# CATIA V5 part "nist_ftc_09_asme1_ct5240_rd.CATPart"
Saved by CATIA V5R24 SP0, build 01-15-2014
Part number: NIST PMI FTC 09 ASME1
Revision: D
Description: NIST PMI test model downloaded from http://go.usa.gov/mGVm
Bounding box of the stored display mesh (mm): x -95.25 to 95.25, y 0 to 3.038, z -139.7 to 139.7
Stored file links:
  C:\work\NIST\DCC_review\nist_ftc_09_asme1_ct5240_rd.CATPart
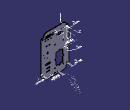
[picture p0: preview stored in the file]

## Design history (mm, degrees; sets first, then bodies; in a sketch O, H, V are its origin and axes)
f4a2d38f3ddc11d3a929006094b99c4b_11 "CATTPSSet"
TTRSSet1
Set1 "MBD_A_PMI"
  Plane1: type Equation, A -0.57735, B 0.57735, C 0.57735, Length 20, RefPoint vertex [face of Chamfer4 | end face of Pad1 | face of Pad1 from Sketch7.L15]
  Point1: type Center, Curve edge [end face of Pad1 | face of Chamfer1]
  Plane2: type OffsetPt, RefPlane face of Pad1 from Sketch7.L15, RefPoint Point1
  Intersect1: ToIntersect1 Chamfer1, ToIntersect2 Plane2
Set2 "MBD_B"
  Sketch1 on end face of Pad1, origin (0, 3.0378, 0), H (-1, 0, 0), V (0, 0, 1)
    arc A1 centre (-50.8, 12.7) radius 34.29 from (-66.509, -17.78) to (-81.28, -3.009) ccw
    point P1 (-50.8, 12.7)
    point P2 (-81.28, -3.009)
    point P3 (-66.509, -17.78)
    line L1 (-64.0699, -20.2137) -> (-63.1677, -17.9758)
    point P5 (-63.1677, -17.9758)
    line L2 (-81.28, -3.009) -> (-83.717, -0.5681)
    line L3 (-83.717, -0.5681) -> (-81.4789, 0.334)
    line L4 (-81.4789, 0.334) -> (-81.28, -3.009)
    polyline C1
    construction line L5 (-50.8, 12.7) -> (-53.3201, 12.7)
    construction line L6 (-50.8, 12.7) -> (-50.8, 10.3697)
    reference projected arc E1 centre (-50.8, 12.7) radius 4.7625 from (-52.578, 17.1182) to (-49.022, 17.1182) ccw from edge [end face of Pad1 | face of Pocket2 from Sketch15.A1]
    point P10 (-63.6219, -19.1025)
    line L7 (-66.509, -17.78) -> (-63.1677, -17.9758)
    line L8 (-66.5086, -17.7802) -> (-64.0704, -20.2149)
    point P12 (-66.5086, -17.7802)
    point P13 (-64.0704, -20.2149)
    radius A1 = 34.29
    distance L5 P3 = 30.48
    distance L6 P2 = 30.48
    length L1 = 2.413
    distance L1 P3 = 3.1722
    angle L1 L7 = 71.3955
    length L8 = 3.4456
    angle L8 L1 = 67
    length L3 = 2.413
    distance L3 P2 = 3.175
    angle L3 L2 = 67
    coincidence: L1 P1, L3 P1, P10 L1, P10 A1, L7 P5, P12 A1, P13 L1
    horizontal: L5 H
    vertical: L6 V
    concentricity: E1 P1
  Sketch2 on end face of Pad1, origin (0, 3.0378, 0), H (-1, 0, 0), V (0, 0, 1)
    reference projected circle E1 centre (57.15, 38.4) radius 3.175 from edge [end face of Pad1 | face of RectPattern2]
    reference projected circle E2 centre (0.15, -101.6) radius 3.175 from edge [end face of Pad1 | face of RectPattern2]
    axis line L1 (0.15, -101.6) -> (57.15, 38.4)
    point P1 (0.15, -101.6)
    point P2 (57.15, 38.4)
    point P3 (28.65, -31.6)
    concentricity: P1 E2, P2 E1
    midpoint: P3 L1
    coincidence: P3 L1
  AxisSystem1 "AF": origin (-28.65, 3.0378, -31.6), X (1, 0, 0), Y (0, 1, 0), Z (0, 0, 1)
  AxisSystem2 "ABC": origin (-82.55, 3.0378, 107.95), X (1, 0, 0), Y (0, 0, -1), Z (0, 1, 0)
Set3 "MBD_C"
  Sketch3 on end face of Pad1, origin (0, 3.0378, 0), H (-1, 0, 0), V (0, 0, 1)
    reference projected circle E1 centre (-50.8, -15.24) radius 1.9844 from edge [end face of Pad1 | face of Hole7]
    point P1 (-50.8, -15.24)
    line L1 (-50.8, -10.16) -> (-50.8, -20.32)
    point P2 (-50.8, -10.16)
    reference projected circle E2 centre (-78.74, 12.7) radius 1.9844 from edge [end face of Pad1 | face of CircPattern1]
    point P4 (-78.74, 12.7)
    line L2 (-83.82, 12.7) -> (-73.66, 12.7)
    point P5 (-83.82, 12.7)
    reference projected circle E3 centre (-70.5566, -7.0566) radius 1.9844 from edge [end face of Pad1 | face of CircPattern1]
    line L3 (-66.9645, -3.4645) -> (-74.1487, -10.6487)
    point P8 (-74.1487, -10.6487)
    point P9 (-70.5566, -7.0566)
    point P10 (-50.8, 12.7)
    point P11 (-66.6352, -10.3194)
    arc A1 centre (-50.8, 12.7) radius 27.94 from (-73.8194, -3.1352) to (-66.6352, -10.3194) ccw
    point P12 (-73.8194, -3.1352)
    construction line L4 (-50.8, 12.7) -> (-89.9713, -15.3816)
    angle L1 L3 = 45
    radius A1 = 27.94
    length L2 = 10.16
    distance P4 P5 = 5.08
    length L3 = 10.16
    distance P9 P8 = 5.08
    length L1 = 10.16
    distance P1 P2 = 5.08
    distance L3 P12 = 5.08
    distance L3 P11 = 5.08
    concentricity: P1 E1, P4 E2, P9 E3
    vertical: L1 V
    coincidence: L1 P1, L2 P4, P9 L3, P10 L3, P10 L2
    horizontal: L2 H
  AxisSystem3 "AGH": origin (50.8, 3.0378, 12.7), X (1, 0, 0), Y (0, 0, -1), Z (0, 1, 0)
  Sketch4 on end face of Pad1, origin (0, 3.0378, 0), H (-1, 0, 0), V (0, 0, 1)
    arc A1 centre (-50.8, 12.7) radius 25.9556 from (-69.1534, -5.6534) to (-72.7556, -1.1436) cw
    point P2 (-69.1534, -5.6534)
    reference projected circle E1 centre (-70.5566, -7.0566) radius 1.9844 from edge [end face of Pad1 | face of CircPattern1]
    reference projected arc E2 centre (-50.8, 12.7) radius 27.94 from (-73.8194, -3.1352) to (-66.6352, -10.3194) ccw from Sketch3.A1
    reference projected line E3 (-66.9645, -3.4645) -> (-74.1487, -10.6487) from Sketch3.L3
    arc A2 centre (-50.8, 12.7) radius 29.9244 from (-71.9597, -8.4597) to (-76.2178, -3.0926) cw
    point P5 (-71.9597, -8.4597)
    reference projected circle E4 centre (-70.5566, -7.0566) radius 1.9844 from edge [end face of Pad1 | face of CircPattern1]
    reference projected arc E5 centre (-50.8, 12.7) radius 27.94 from (-73.8194, -3.1352) to (-66.6352, -10.3194) ccw from Sketch3.A1
    reference projected line E6 (-66.9645, -3.4645) -> (-74.1487, -10.6487) from Sketch3.L3
    tangency: A1 E1, A2 E4
    concentricity: A1 E2, A2 E5
    coincidence: P2 E3, P5 E6
  Sketch5 on end face of Pad1, origin (0, 3.0378, 0), H (-1, 0, 0), V (0, 0, 1)
    line L1 (-50.8, 12.7) -> (-77.7835, -8.4552)
    point P1 (-50.8, 12.7)
    point P3 (-74.3496, -5.763)
    reference projected arc E1 centre (-50.8, 12.7) radius 29.9244 from (-76.2178, -3.0926) to (-71.9597, -8.4597) ccw from Sketch4.A2
    reference projected point E2 (-50.8, 12.7) from vertex [YZ plane of AxisSystem3 | ZX plane of AxisSystem3 | XY plane of AxisSystem3]
    point P4 (-71.2263, -3.3144)
    reference projected arc E3 centre (-50.8, 12.7) radius 25.9556 from (-72.7556, -1.1436) to (-69.1534, -5.6534) ccw from Sketch4.A1
    coincidence: P3 L1, P3 E1, P1 E2, P4 L1, P4 E3
Set4 "MBD_D"
  Sketch6 on end face of Pad1, origin (0, 3.0378, 0), H (-1, 0, 0), V (0, 0, 1)
    reference projected circle E1 centre (-66.0374, 91.44) radius 3.5687 from edge [end face of Pad1 | face of RectPattern5]
    point P1 (-66.0374, 91.44)
    line L1 (-71.1174, 91.44) -> (-60.9574, 91.44)
    point P2 (-71.1174, 91.44)
    line L2 (-66.0374, 96.52) -> (-66.0374, 86.36)
    point P4 (-66.0374, 96.52)
    length L2 = 10.16
    distance P4 L1 = 5.08
    length L1 = 10.16
    distance P2 L2 = 5.08
    concentricity: P1 E1
    horizontal: L1 H
    coincidence: P1 L1, P1 L2
    vertical: L2 V
  AxisSystem4 "ADB": origin (-31.75, 3.0378, 91.44), X (1, 0, 0), Y (0, 0, -1), Z (0, 1, 0)
  AxisSystem5 "ABC": origin (-82.55, 3.0378, 107.95), X (1, 0, 0), Y (0, 0, -1), Z (0, 1, 0)
Set5 "MBD_A"
  AxisSystem6 "ABC": origin (-82.55, 3.0378, 107.95), X (1, 0, 0), Y (0, 0, -1), Z (0, 1, 0)
Set6
  Point2: type Center, Curve edge [end face of Pad1 | face of Chamfer1]
  Point3: type Center, Curve edge [end face of Pad1 | face of Pocket2 from Sketch15.A1]
  Point4: type Center, Curve edge [end face of Pad1 | face of Hole5]
Body1 (main body)
  Sketch7 on zx-plane, origin (0, 0, 0), H (-1, 0, 0), V (0, 0, 1)
    line L1 (-74.6125, 139.7) -> (74.6125, 139.7)
    line L2 (95.25, 117.475) -> (95.25, -117.475)
    construction line L3 (74.6125, -139.7) -> (-74.6125, -139.7)
    line L4 (-95.25, -117.475) -> (-95.25, 117.475)
    construction line L5 (0, -160) -> (0, 150)
    axis line L6 (150, 0) -> (-110, 0)
    line L7 (-74.6125, 139.7) -> (-74.6125, 117.475)
    line L8 (-74.6125, 117.475) -> (-95.25, 117.475)
    line L9 (74.6125, 139.7) -> (74.6125, 117.475)
    line L10 (74.6125, 117.475) -> (95.25, 117.475)
    line L11 (-95.25, -117.475) -> (-74.6125, -117.475)
    line L12 (-74.6125, -117.475) -> (-74.6125, -139.7)
    line L13 (95.25, -117.475) -> (74.6125, -117.475)
    line L14 (74.6125, -117.475) -> (74.6125, -139.7)
    line L15 (-74.6125, -139.7) -> (74.6125, -139.7)
    distance L1 L3 = 279.4
    distance L4 L2 = 190.5
    distance L5 L4 = 95.25
    distance L3 L6 = 139.7
    length L4 = 234.95
    length L3 = 149.225
    distance L12 L5 = 74.6125
    distance L6 L11 = 117.475
    horizontal: L6 H, L3 H, L1 H, L8 H, L10 H, L11 H, L13 H
    coincidence: L5 V, L6 H, L10 L8, L14 L9, L11 L13, L12 L7
    vertical: L2 V, L4 V, L14 V, L9 V, L12 V, L7 V
  Pad1: profile Sketch7, direction (0, 1, 0), length 3.0378
  Sketch8 on end face of Pad1, origin (75.874, 3.0378, 103.1133), H (1, 0, 0), V (0, 0, -1)
    point P1 (6.676, -4.8367)
    reference intersected line E1 through (-75.874, 0) direction (0, 1) from yz-plane
    reference intersected line E2 through (0, 103.1133) direction (1, 0) from xy-plane
    distance P1 E1 = 82.55
    distance E2 P1 = 107.95
  Hole1: placed by Sketch8, at (82.55, 3.0378, 107.95) direction (0, -1, 0), diameter 5.9436, through (limit type 6)
  Fillet1: radius 6.35, on edge [face of Pad1 from Sketch7.L8 | face of Pad1 from Sketch7.L7]; edge [face of Pad1 from Sketch7.L9 | face of Pad1 from Sketch7.L10]; edge [face of Pad1 from Sketch7.L13 | face of Pad1 from Sketch7.L14]; edge [face of Pad1 from Sketch7.L12 | face of Pad1 from Sketch7.L11]
  Sketch9 on end face of Pad1, origin (32.8752, 3.0378, 131.8981), H (1, 0, 0), V (0, 0, -1)
    point P1 (-13.8252, 261.4381)
    reference intersected line E2 through (-32.8752, 0) direction (0, 1) from yz-plane
    reference intersected line E3 through (0, 131.8981) direction (1, 0) from xy-plane
    distance P1 E2 = 19.05
    distance E3 P1 = 129.54
  Hole2: placed by Sketch9, at (19.05, 3.0378, -129.54) direction (0, -1, 0), diameter 6.35, through (limit type 6)
  RectPattern1: of Hole2, direction 1 instances 3, spacing 19.05, along edge [face of Pad1 from Sketch7.L1 | end face of Pad1] reversed
  Sketch10 on end face of Pad1, origin (53.7045, 3.0378, 105.0288), H (1, 0, 0), V (0, 0, -1)
    point P1 (-110.8545, 206.6288)
    reference intersected line E1 through (-53.7045, 0) direction (0, 1) from yz-plane
    reference intersected line E2 through (0, 105.0288) direction (1, 0) from xy-plane
    distance P1 E1 = 57.15
    distance E2 P1 = 101.6
  Hole3: placed by Sketch10, at (-57.15, 3.0378, -101.6) direction (0, -1, 0), diameter 6.35, through (limit type 6)
  RectPattern2: of Hole3, direction 1 instances 2, spacing 57, along edge [face of Pad1 from Sketch7.L1 | end face of Pad1], direction 2 instances 2, spacing 140, along edge [face of Pad1 from Sketch7.L4 | end face of Pad1] reversed
  Sketch11 on end face of Pad1, origin (0, 3.0378, 0), H (-1, 0, 0), V (0, 0, 1)
    point P1 (5.649, -11.6078)
    line L1 (5.649, -11.6078) -> (24.3053, -11.6078)
    line L2 (55.649, -11.6078) -> (55.649, -45.2528)
    line L3 (55.649, -91.6078) -> (37.0053, -91.6078)
    line L4 (5.649, -91.6078) -> (5.649, -57.9528)
    point P2 (55.649, -11.6078)
    point P4 (5.649, -91.6078)
    arc A1 centre (55.649, -51.6028) radius 6.35 from (55.649, -57.9528) to (55.649, -45.2528) ccw
    point P5 (55.649, -51.6028)
    arc A2 centre (30.6553, -11.6078) radius 6.35 from (37.0053, -11.6078) to (24.3053, -11.6078) ccw
    point P6 (30.6553, -11.6078)
    arc A3 centre (5.649, -51.6028) radius 6.35 from (5.649, -45.2528) to (5.649, -57.9528) ccw
    point P7 (5.649, -51.6028)
    arc A4 centre (30.6553, -91.6078) radius 6.35 from (24.3053, -91.6078) to (37.0053, -91.6078) ccw
    point P8 (30.6553, -91.6078)
    construction line L5 (30.6553, 11.6851) -> (30.6553, -11.6078)
    axis line L6 (55.649, -51.6028) -> (5.649, -51.6028)
    line L7 (55.649, -57.9528) -> (55.649, -91.6078)
    line L8 (5.649, -45.2528) -> (5.649, -11.6078)
    line L9 (37.0053, -11.6078) -> (55.649, -11.6078)
    line L10 (24.3053, -91.6078) -> (5.649, -91.6078)
    reference intersected line E1 through (0, 0) direction (-1, 0) from xy-plane
    reference intersected line E2 through (0, 0) direction (0, -1) from yz-plane
    distance L6 L3 = 40.005
    distance L5 L4 = 25.0063
    radius A2 = 6.35
    radius A1 = 6.35
    radius A4 = 6.35
    radius A3 = 6.35
    distance P4 P1 = 80
    distance P1 P2 = 50
    distance L9 E1 = 11.6078
    distance L8 E2 = 5.649
    horizontal: L1 H, L3 H
    vertical: L2 V, L4 V
    coincidence: P7 L4, P6 L1, P8 L3, P5 L2, P8 L5, L2 L7, L9 L1, L3 L10, L8 L4
  Pocket1: profile Sketch11, direction (0, -1, 0), through (limit type 6)
  RectPattern3: of Hole1, direction 1 instances 2, spacing 165.1, along edge [face of Pad1 from Sketch7.L1 | end face of Pad1] reversed, direction 2 instances 2, spacing 215.9, along edge [face of Pad1 from Sketch7.L4 | end face of Pad1]
  Chamfer1: length 0.762, second length 0.762, on edge [end face of Pad1 | face of Hole1]; edge [end face of Pad1 | face of RectPattern3] (x3)
  Chamfer2: length 6.35, second length 6.35, on edge [face of Pad1 from Sketch7.L4 | face of Pad1 from Sketch7.L8]; edge [face of Pad1 from Sketch7.L10 | face of Pad1 from Sketch7.L2]; edge [face of Pad1 from Sketch7.L11 | face of Pad1 from Sketch7.L4]; edge [face of Pad1 from Sketch7.L2 | face of Pad1 from Sketch7.L13]
  Chamfer3: length 12.7, angle 30, on edge [face of Pad1 from Sketch7.L7 | face of Pad1 from Sketch7.L1]; edge [face of Pad1 from Sketch7.L1 | face of Pad1 from Sketch7.L9]
  Chamfer4: length 12.7, angle 30, on edge [face of Pad1 from Sketch7.L15 | face of Pad1 from Sketch7.L12]; edge [face of Pad1 from Sketch7.L14 | face of Pad1 from Sketch7.L15]
  Sketch12 on end face of Pad1, origin (53.7613, 3.0378, -81.0134), H (1, 0, 0), V (0, 0, -1)
    point P1 (-104.5613, -172.4534)
    reference intersected line E1 through (0, -81.0134) direction (1, 0) from xy-plane
    reference intersected line E2 through (-53.7613, 0) direction (0, 1) from yz-plane
    distance P1 E1 = 91.44
    distance E2 P1 = 50.8
  Hole4: placed by Sketch12, at (-50.8, 3.0378, 91.44) direction (0, -1, 0), diameter 5.6134, through (limit type 6)
  RectPattern4: of Hole4, direction 1 instances 2, spacing 38.1, along edge [face of Pad1 from Sketch7.L15 | end face of Pad1] reversed, direction 2 instances 2, spacing 215.9
  Sketch13 on end face of Pad1, origin (33.0099, 3.0378, -92.3254), H (1, 0, 0), V (0, 0, -1)
    point P1 (-64.7599, -183.7654)
    reference intersected line E1 through (0, -92.3254) direction (1, 0) from xy-plane
    reference intersected line E2 through (-33.0099, 0) direction (0, 1) from yz-plane
    distance P1 E1 = 91.44
    distance E2 P1 = 31.75
  Hole5: placed by Sketch13, at (-31.75, 3.0378, 91.44) direction (0, -1, 0), diameter 19.05, through (limit type 6)
  Sketch14 on end face of Pad1, origin (-47.4372, 3.0378, -73.8358), H (1, 0, 0), V (0, 0, -1)
    point P1 (75.3745, -165.2758)
    reference intersected line E1 through (0, -73.8358) direction (1, 0) from xy-plane
    reference intersected line E2 through (47.4372, 0) direction (0, 1) from yz-plane
    distance E1 P1 = 91.44
    distance E2 P1 = 27.9374
  Hole6: placed by Sketch14, at (27.9374, 3.0378, 91.44) direction (0, -1, 0), diameter 7.1374, through (limit type 6)
  RectPattern5: of Hole6, direction 1 instances 3, spacing 19.05, along edge [face of Pad1 from Sketch7.L15 | end face of Pad1] reversed, direction 2 instances 2, spacing 215.9
  Sketch15 on end face of Pad1, origin (0, 3.0378, 0), H (-1, 0, 0), V (0, 0, 1)
    arc A1 centre (-50.8, 12.7) radius 4.7625 from (-52.578, 17.1182) to (-49.022, 17.1182) ccw
    point P1 (-50.8, 12.7)
    axis line L1 (-50.8, 12.7) -> (-50.8, 29.6508)
    line L2 (-52.578, 20.32) -> (-52.578, 17.1182)
    line L3 (-49.022, 20.32) -> (-49.022, 17.1182)
    arc A2 centre (-50.8, 20.32) radius 1.778 from (-49.022, 20.32) to (-52.578, 20.32) ccw
    point P3 (-50.8, 20.32)
    point P4 (-49.022, 20.32)
    reference intersected line E1 through (0, 0) direction (-1, 0) from xy-plane
    reference intersected line E2 through (0, 0) direction (0, -1) from yz-plane
    radius A1 = 4.7625
    distance L3 L2 = 3.556
    distance P1 P3 = 7.62
    distance E1 P1 = 12.7
    distance E2 L1 = 50.8
    vertical: L1 V, L2 V, L3 V
    coincidence: P3 L1, A2 P4, P4 L3
    tangency: A2 L3, A2 L2
  Pocket2: profile Sketch15, direction (0, -1, 0), through (limit type 6)
  Sketch16 on end face of Pad1, origin (-52.5866, 3.0378, 15.7994), H (1, 0, 0), V (0, 0, -1)
    point P1 (103.3866, 31.0394)
    reference intersected line E1 through (0, 15.7994) direction (1, 0) from xy-plane
    reference intersected line E2 through (52.5866, 0) direction (0, 1) from yz-plane
    distance P1 E1 = 15.24
    distance E2 P1 = 50.8
  Hole7: placed by Sketch16, at (50.8, 3.0378, -15.24) direction (0, -1, 0), diameter 3.9688, through (limit type 6)
  CircPattern1: of Hole7, instances 3, angular step 45, axis from face of Pocket2 from Sketch15.A1
  Sketch17 on end face of Pad1, origin (0, 3.0378, 0), H (-1, 0, 0), V (0, 0, 1)
    construction line L1 (-57.15, -95.25) -> (-38.1, -95.25)
    line L2 (-57.15, -92.075) -> (-38.1, -92.075)
    line L3 (-38.1, -98.425) -> (-57.15, -98.425)
    arc A1 centre (-38.1, -95.25) radius 3.175 from (-38.1, -92.075) to (-38.1, -98.425) cw
    arc A2 centre (-57.15, -95.25) radius 3.175 from (-57.15, -98.425) to (-57.15, -92.075) cw
    axis line L4 (-47.625, -92.075) -> (-47.625, -98.425)
    point P7 (-47.625, -92.075)
    point P8 (-47.625, -98.425)
    reference intersected line E1 through (0, 0) direction (-1, 0) from xy-plane
    reference intersected line E2 through (0, 0) direction (0, -1) from yz-plane
    distance L1 L2 = 3.175
    distance A2 A1 = 25.4
    distance E1 L1 = 95.25
    distance L4 E2 = 47.625
    horizontal: L1 H
    tangency: A1 L2, A2 L2, A1 L3, A2 L3
    vertical: L4 V
    midpoint: P7 L2, L3 P8
  Pocket3: profile Sketch17, direction (0, -1, 0), through (limit type 6)
  RectPattern6: of Pocket3, direction 1 instances 2, spacing 19.05, along edge [face of Pad1 from Sketch7.L2 | end face of Pad1], direction 2 instances 2, spacing 215.9
  Sketch18 on end face of Pad1, origin (0, 3.0378, 0), H (-1, 0, 0), V (0, 0, 1)
    construction line L1 (-61.9125, -50.8) -> (-33.3375, -50.8)
    line L2 (-61.9125, -46.0375) -> (-33.3375, -46.0375)
    line L3 (-33.3375, -55.5625) -> (-61.9125, -55.5625)
    arc A1 centre (-33.3375, -50.8) radius 4.7625 from (-33.3375, -46.0375) to (-33.3375, -55.5625) cw
    arc A2 centre (-61.9125, -50.8) radius 4.7625 from (-61.9125, -55.5625) to (-61.9125, -46.0375) cw
    axis line L4 (-47.625, -46.0375) -> (-47.625, -55.5625)
    point P7 (-47.625, -46.0375)
    point P8 (-47.625, -55.5625)
    reference intersected line E1 through (0, 0) direction (-1, 0) from xy-plane
    reference intersected line E2 through (0, 0) direction (0, -1) from yz-plane
    distance L1 L2 = 4.7625
    distance A2 A1 = 38.1
    distance L1 E1 = 50.8
    distance L4 E2 = 47.625
    horizontal: L1 H
    tangency: A1 L2, A2 L2, A1 L3, A2 L3
    coincidence: P7 L2, P8 L3
    vertical: L4 V
    midpoint: P8 L3, P7 L2
  Pocket4: profile Sketch18, direction (0, -1, 0), through (limit type 6)
  Sketch19 on end face of Pad1, origin (83.475, 3.0378, 19.7164), H (1, 0, 0), V (0, 0, -1)
    point P1 (-168.565, 38.7664)
    reference intersected line E1 through (0, 19.7164) direction (1, 0) from xy-plane
    reference intersected line E2 through (-83.475, 0) direction (0, 1) from yz-plane
    distance E1 P1 = 19.05
    distance E2 P1 = 85.09
  Hole8: placed by Sketch19, at (-85.09, 3.0378, -19.05) direction (0, -1, 0), diameter 6.35, through (limit type 6)
  RectPattern7: of Hole8, direction 1 instances 3, spacing 19.05, along edge [face of Pad1 from Sketch7.L4 | end face of Pad1] reversed, direction 2 instances 2, spacing 215.9
  Sketch20 on end face of Pad1, origin (46.5928, 3.0378, -111.2191), H (1, 0, 0), V (0, 0, -1)
    point P1 (-102.4728, -221.7091)
    reference intersected line E1 through (-46.5928, 0) direction (0, 1) from yz-plane
    reference intersected line E2 through (0, -111.2191) direction (1, 0) from xy-plane
    distance P1 E1 = 55.88
    distance P1 E2 = 110.49
  Hole9: placed by Sketch20, at (-55.88, 3.0378, 110.49) direction (0, -1, 0), diameter 3.9688, through (limit type 6)
  RectPattern8: of Hole9, direction 1 instances 2, spacing 10.16, along edge [face of Pad1 from Sketch7.L15 | end face of Pad1] reversed, direction 2 instances 2, spacing 215.9
  RectPattern9: of RectPattern8, direction 1 instances 2, spacing 38.1, along edge [face of Pad1 from Sketch7.L15 | end face of Pad1] reversed, direction 2 instances 2, spacing 215.9
  Sketch21 on end face of Pad1, origin (-44.0436, 3.0378, -67.034), H (1, 0, 0), V (0, 0, -1)
    point P1 (82.1436, -124.184)
    reference intersected line E1 through (44.0436, 0) direction (0, 1) from yz-plane
    reference intersected line E2 through (0, -67.034) direction (1, 0) from xy-plane
    distance E1 P1 = 38.1
    distance E2 P1 = 57.15
  Hole10: placed by Sketch21, at (38.1, 3.0378, 57.15) direction (0, -1, 0), diameter 8.001, through (limit type 6)
  RectPattern10: of Hole10, direction 1 instances 2, spacing 19.05, along edge [face of Pad1 from Sketch7.L15 | end face of Pad1] reversed, direction 2 instances 2, spacing 215.9
  Fillet2: radius 3.175, on edge [face of Pocket1 from Sketch11.L10 | face of Pocket1 from Sketch11.L4]; edge [face of Pocket1 from Sketch11.L8 | face of Pocket1 from Sketch11.L1]; edge [face of Pocket1 from Sketch11.L9 | face of Pocket1 from Sketch11.L2]; edge [face of Pocket1 from Sketch11.L7 | face of Pocket1 from Sketch11.L3]
  Sketch22 on end face of Pad1, origin (0, 3.0378, 0), H (-1, 0, 0), V (0, 0, 1)
    point P1 (-12.7, 118.11)
    reference intersected line E1 through (0, 0) direction (0, -1) from yz-plane
    reference intersected line E2 (-74.6125, 139.7) -> (74.6125, 139.7) from face of Pad1 from Sketch7.L1
    point P2 (-12.7, 118.11)
    point P3 (-12.7, 118.11)
    point P4 (-26.2068, 116.7906)
    point P5 (-32.4699, 114.5929)
    point P6 (-37.6134, 113.9143)
    point P7 (-38.7059, 115.0068)
    point P8 (-15.8025, 118.11)
    point P9 (-15.8025, 106.8665)
    point P10 (-15.8025, 118.11)
    point P11 (-16.7397, 106.501)
    point P12 (-15.8025, 106.8665)
    point P13 (-26.2068, 116.7906)
    point P14 (-16.7397, 106.501)
    point P15 (-32.4699, 103.11)
    point P16 (-32.4699, 114.5929)
    point P17 (-29.3377, 103.11)
    point P18 (-32.4699, 103.11)
    point P19 (-29.3377, 114.5181)
    point P20 (-29.3377, 103.11)
    point P21 (-28.62, 114.8343)
    point P22 (-29.3377, 114.5181)
    point P23 (-18.3552, 103.7339)
    point P24 (-28.62, 114.8343)
    point P25 (-18.3552, 103.7339)
    point P26 (-12.7, 105.9479)
    point P27 (-12.7, 105.9479)
    point P28 (-37.6134, 103.11)
    point P29 (-34.4811, 103.11)
    point P30 (-37.6134, 113.9143)
    point P31 (-37.6134, 103.11)
    point P32 (-53.4174, 115.0068)
    point P33 (-38.7059, 115.0068)
    point P34 (-53.4174, 115.0068)
    point P35 (-53.3599, 112.1904)
    point P36 (-44.3081, 112.1904)
    point P37 (-53.3599, 112.1904)
    point P38 (-43.9641, 103.11)
    point P39 (-44.3081, 112.1904)
    point P40 (-69.5674, 103.11)
    point P41 (-43.9641, 103.11)
    point P42 (-69.5674, 106.271)
    point P43 (-69.5674, 103.11)
    point P44 (-63.1581, 106.271)
    point P45 (-69.5674, 106.271)
    point P46 (-63.1581, 118.11)
    point P47 (-63.1581, 106.271)
    point P48 (-60.0556, 118.11)
    point P49 (-63.1581, 118.11)
    point P50 (-60.0556, 106.271)
    point P51 (-60.0556, 118.11)
    point P52 (-44.3655, 106.271)
    point P53 (-60.0556, 106.271)
    point P54 (-44.3655, 106.271)
    point P55 (-44.2506, 109.0871)
    point P56 (-53.8773, 109.0871)
    point P57 (-44.2506, 109.0871)
    point P58 (-53.8773, 118.11)
    point P59 (-53.8773, 109.0871)
    point P60 (-38.6768, 118.11)
    point P61 (-53.8773, 118.11)
    point P62 (-34.4811, 113.9143)
    point P63 (-38.6768, 118.11)
    point P64 (-34.4811, 103.11)
    point P65 (-34.4811, 113.9143)
    point P66 (-12.7, 118.11)
    point P67 (-12.7, 118.11)
    line L1 (-34.4811, 103.11) -> (-34.4811, 113.9143)
    arc A1 centre (-38.6768, 113.9143) radius 4.1957 from (-34.4811, 113.9143) to (-38.6768, 118.11) ccw
    line L2 (-38.6768, 118.11) -> (-53.8773, 118.11)
    arc A2 centre (-53.1589, 113.5985) radius 4.5683 from (-53.8773, 118.11) to (-53.8773, 109.0871) ccw
    line L3 (-53.8773, 109.0871) -> (-44.2506, 109.0871)
    arc A3 centre (-44.2506, 107.6767) radius 1.4104 from (-44.3655, 106.271) to (-44.2506, 109.0871) ccw
    line L4 (-44.3655, 106.271) -> (-60.0556, 106.271)
    line L5 (-60.0556, 106.271) -> (-60.0556, 118.11)
    line L6 (-60.0556, 118.11) -> (-63.1581, 118.11)
    line L7 (-63.1581, 118.11) -> (-63.1581, 106.271)
    line L8 (-63.1581, 106.271) -> (-69.5674, 106.271)
    line L9 (-69.5674, 106.271) -> (-69.5674, 103.11)
    line L10 (-69.5674, 103.11) -> (-43.9641, 103.11)
    arc A4 centre (-43.9641, 107.6567) radius 4.5467 from (-43.9641, 103.11) to (-44.3081, 112.1904) ccw
    line L11 (-44.3081, 112.1904) -> (-53.3599, 112.1904)
    arc A5 centre (-53.2372, 113.6017) radius 1.4166 from (-53.4174, 115.0068) to (-53.3599, 112.1904) ccw
    line L12 (-53.4174, 115.0068) -> (-38.7059, 115.0068)
    line L13 (-37.6134, 113.9143) -> (-37.6134, 103.11)
    line L14 (-37.6134, 103.11) -> (-34.4811, 103.11)
    line L15 (-12.7, 118.11) -> (-12.7, 105.9479)
    arc A6 centre (-15.961, 105.9479) radius 3.261 from (-18.3552, 103.7339) to (-12.7, 105.9479) ccw
    line L16 (-18.3552, 103.7339) -> (-28.62, 114.8343)
    arc A7 centre (-28.9245, 114.5528) radius 0.4146 from (-28.62, 114.8343) to (-29.3377, 114.5181) ccw
    line L17 (-29.3377, 114.5181) -> (-29.3377, 103.11)
    line L18 (-29.3377, 103.11) -> (-32.4699, 103.11)
    line L19 (-32.4699, 103.11) -> (-32.4699, 114.5929)
    line L20 (-26.2068, 116.7906) -> (-16.7397, 106.501)
    arc A8 centre (-16.3424, 106.8665) radius 0.5399 from (-16.7397, 106.501) to (-15.8025, 106.8665) ccw
    line L21 (-15.8025, 106.8665) -> (-15.8025, 118.11)
    line L22 (-15.8025, 118.11) -> (-12.7, 118.11)
    arc A9 centre (-38.7059, 113.9143) radius 1.0926 from (-37.6134, 113.9143) to (-38.7059, 115.0068) ccw
    arc A10 centre (-28.9528, 114.5929) radius 3.5171 from (-26.2068, 116.7906) to (-32.4699, 114.5929) ccw
    distance P1 E1 = 12.7
    distance E2 P1 = 21.59
    fix: P4, P5, P6, P7, P8, P9, P10, P11, P12, P13, P14, P15, P16, P17, P18, P19, P20, P21, P22, P23, P24, P25, P26, P27, P28, P29, P30, P31, P32, P33, P34, P35, P36, P37, P38, P39, P40, P41, P42, P43, P44, P45, P46, P47, P48, P49, P50, P51, P52, P53, P54, P55, P56, P57, P58, P59, P60, P61, P62, P63, P64, P65, L1, A1, L2, A2, L3, A3, L4, L5, L6, L7, L8, L9, L10, A4, L11, A5, L12, L13, L14, A6, L16, A7, L17, L18, L19, L20, A8, L21, A9, A10, L22, L15, P2
    coincidence: P66 P67
  Pocket5: profile Sketch22, direction (0, -1, 0), length 1.27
